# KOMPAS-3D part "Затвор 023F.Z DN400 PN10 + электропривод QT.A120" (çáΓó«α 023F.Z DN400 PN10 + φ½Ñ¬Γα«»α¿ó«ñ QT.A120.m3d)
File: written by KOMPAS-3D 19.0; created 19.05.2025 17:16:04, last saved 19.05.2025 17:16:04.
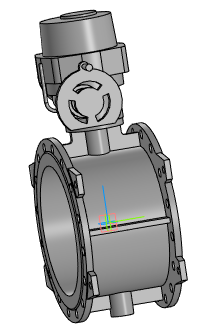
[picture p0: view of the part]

Document properties: Полное имя файла: Затвор 023F.Z DN400 PN10 + электропривод QT.A120.a3d

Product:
- Part/product: Затвор 023F.Z DN400 PN10 + электропривод QT.A120
    Масса: 283.147

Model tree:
1. Операция без истории:1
